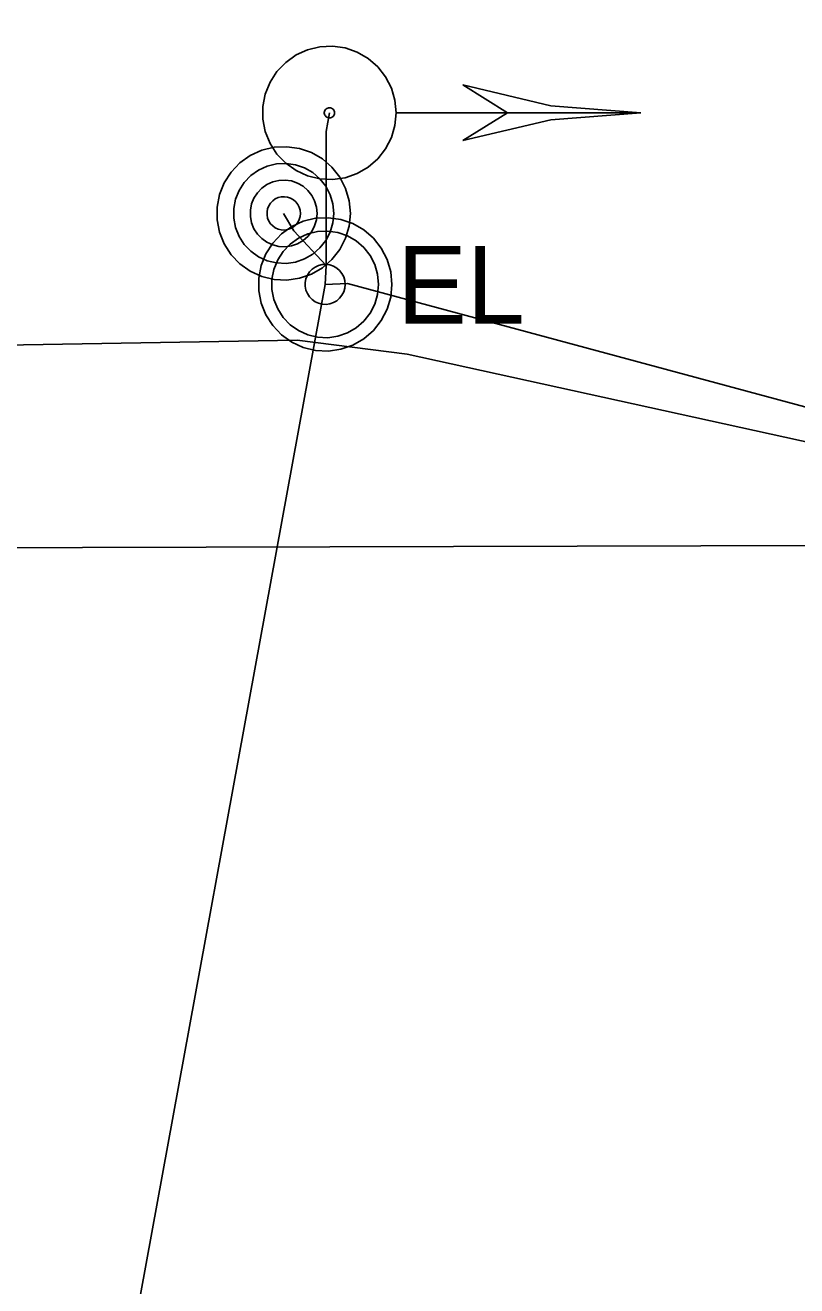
# Model space of a CAD drawing. Extents: x 600849 to 606371, y 330010 to 403088.
# Drawn here: x 604019.5 to 604057.6, y 339253 to 339315.3 of the extents above; entities that cross this region are included whole.
import ezdxf

# ---------------------------------------------------------------- set-up
doc = ezdxf.new("R2010")
doc.units = 0
for name, color, linetype in [('E_MISCPROP', 7, 'Continuous'), ('E_SIG', 7, 'Continuous'), ('E_SIG_Conduit', 7, 'Continuous'), ('E_UTL_E', 7, 'Continuous'), ('E_UTL_E_UG', 7, 'Continuous'), ('E_UTL_T_UG', 7, 'Continuous')]:
    doc.layers.add(name, color=color, linetype=linetype)

msp = doc.modelspace()

# ---------------------------------------------------------------- linework, layer by layer
at = {"layer": 'E_MISCPROP'}
for points in [[(604035.542, 339305.951), (604035.483, 339306.576), (604035.306, 339307.178), (604035.018, 339307.735), (604034.631, 339308.228), (604034.156, 339308.639), (604033.613, 339308.953), (604033.02, 339309.158), (604032.399, 339309.247), (604031.773, 339309.218), (604031.163, 339309.07), (604030.592, 339308.809), (604030.081, 339308.445), (604029.648, 339307.991), (604029.309, 339307.463), (604029.076, 339306.881), (604028.957, 339306.265), (604028.957, 339305.637), (604029.076, 339305.021), (604029.309, 339304.439), (604029.648, 339303.911), (604030.081, 339303.457), (604030.592, 339303.093), (604031.163, 339302.833), (604031.773, 339302.685), (604032.399, 339302.655), (604033.02, 339302.744), (604033.613, 339302.949), (604034.156, 339303.263), (604034.631, 339303.674), (604035.018, 339304.167), (604035.306, 339304.725), (604035.483, 339305.327), (604035.542, 339305.951)], [(604034.717, 339305.951), (604034.673, 339306.42), (604034.54, 339306.871), (604034.324, 339307.289), (604034.034, 339307.659), (604033.678, 339307.967), (604033.27, 339308.202), (604032.826, 339308.356), (604032.36, 339308.423), (604031.89, 339308.401), (604031.433, 339308.29), (604031.005, 339308.095), (604030.622, 339307.822), (604030.297, 339307.481), (604030.042, 339307.085), (604029.868, 339306.648), (604029.778, 339306.186), (604029.778, 339305.716), (604029.868, 339305.254), (604030.042, 339304.817), (604030.297, 339304.421), (604030.622, 339304.081), (604031.005, 339303.808), (604031.433, 339303.612), (604031.89, 339303.501), (604032.36, 339303.479), (604032.826, 339303.546), (604033.27, 339303.7), (604033.678, 339303.935), (604034.034, 339304.243), (604034.324, 339304.613), (604034.54, 339305.031), (604034.673, 339305.483), (604034.717, 339305.951)], [(604033.892, 339305.951), (604033.862, 339306.263), (604033.774, 339306.564), (604033.63, 339306.843), (604033.436, 339307.09), (604033.199, 339307.295), (604032.928, 339307.452), (604032.631, 339307.555), (604032.321, 339307.599), (604032.007, 339307.584), (604031.703, 339307.51), (604031.417, 339307.38), (604031.162, 339307.198), (604030.945, 339306.971), (604030.776, 339306.707), (604030.659, 339306.416), (604030.6, 339306.108), (604030.6, 339305.794), (604030.659, 339305.486), (604030.776, 339305.195), (604030.945, 339304.931), (604031.162, 339304.704), (604031.417, 339304.522), (604031.703, 339304.392), (604032.007, 339304.318), (604032.321, 339304.303), (604032.631, 339304.348), (604032.928, 339304.45), (604033.199, 339304.607), (604033.436, 339304.813), (604033.63, 339305.059), (604033.774, 339305.338), (604033.862, 339305.639), (604033.892, 339305.951)], [(604033.067, 339305.951), (604033.052, 339306.107), (604033.008, 339306.258), (604032.936, 339306.397), (604032.839, 339306.52), (604032.721, 339306.623), (604032.585, 339306.702), (604032.437, 339306.753), (604032.282, 339306.775), (604032.125, 339306.768), (604031.972, 339306.731), (604031.83, 339306.666), (604031.702, 339306.575), (604031.594, 339306.461), (604031.509, 339306.329), (604031.451, 339306.184), (604031.421, 339306.03), (604031.421, 339305.873), (604031.451, 339305.719), (604031.509, 339305.573), (604031.594, 339305.441), (604031.702, 339305.328), (604031.83, 339305.237), (604031.972, 339305.172), (604032.125, 339305.135), (604032.282, 339305.127), (604032.437, 339305.149), (604032.585, 339305.201), (604032.721, 339305.279), (604032.839, 339305.382), (604032.936, 339305.505), (604033.008, 339305.645), (604033.052, 339305.795), (604033.067, 339305.951)]]:
    msp.add_lwpolyline(points, dxfattribs=at)
at = {"layer": 'E_SIG'}
for points in [[(604037.803, 339310.921), (604037.743, 339311.545), (604037.566, 339312.147), (604037.279, 339312.705), (604036.891, 339313.198), (604036.417, 339313.609), (604035.874, 339313.923), (604035.281, 339314.128), (604034.66, 339314.217), (604034.033, 339314.187), (604033.423, 339314.039), (604032.853, 339313.779), (604032.342, 339313.415), (604031.909, 339312.961), (604031.57, 339312.433), (604031.336, 339311.851), (604031.218, 339311.235), (604031.218, 339310.607), (604031.336, 339309.991), (604031.57, 339309.409), (604031.909, 339308.881), (604032.342, 339308.427), (604032.853, 339308.063), (604033.423, 339307.802), (604034.033, 339307.654), (604034.66, 339307.625), (604035.281, 339307.714), (604035.874, 339307.919), (604036.417, 339308.233), (604036.891, 339308.644), (604037.279, 339309.137), (604037.566, 339309.694), (604037.743, 339310.296), (604037.803, 339310.921)], [(604043.303, 339310.92), (604041.103, 339312.297)], [(604049.903, 339310.921), (604045.449, 339311.267), (604041.103, 339312.296)], [(604034.755, 339310.921), (604034.751, 339310.969), (604034.737, 339311.015), (604034.715, 339311.057), (604034.685, 339311.095), (604034.649, 339311.126), (604034.608, 339311.15), (604034.562, 339311.166), (604034.515, 339311.173), (604034.467, 339311.171), (604034.42, 339311.159), (604034.377, 339311.139), (604034.337, 339311.112), (604034.304, 339311.077), (604034.278, 339311.037), (604034.261, 339310.992), (604034.251, 339310.945), (604034.251, 339310.897), (604034.261, 339310.85), (604034.278, 339310.805), (604034.304, 339310.765), (604034.337, 339310.73), (604034.377, 339310.702), (604034.42, 339310.682), (604034.467, 339310.671), (604034.515, 339310.669), (604034.562, 339310.676), (604034.608, 339310.691), (604034.649, 339310.715), (604034.685, 339310.747), (604034.715, 339310.784), (604034.737, 339310.827), (604034.751, 339310.873), (604034.755, 339310.921)], [(604049.902, 339310.92), (604037.861, 339310.92)], [(604049.903, 339310.921), (604045.449, 339310.575), (604041.103, 339309.546)], [(604041.103, 339309.548), (604043.303, 339310.92)]]:
    msp.add_lwpolyline(points, dxfattribs=at)
at = {"layer": 'E_SIG_Conduit'}
msp.add_lwpolyline([(604071.892, 339291.801), (604067.502, 339292.591), (604038.342, 339299.001), (604032.902, 339299.691), (603983.63, 339298.839), (603940.372, 339298.091), (603941.812, 339302.101), (603953.592, 339343.861), (603947.372, 339356.301)], dxfattribs=at)
at = {"layer": 'E_UTL_E'}
for points in [[(604037.594, 339302.443), (604037.534, 339303.067), (604037.357, 339303.669), (604037.07, 339304.227), (604036.682, 339304.72), (604036.208, 339305.131), (604035.664, 339305.444), (604035.072, 339305.65), (604034.451, 339305.739), (604033.824, 339305.709), (604033.214, 339305.561), (604032.644, 339305.3), (604032.133, 339304.937), (604031.7, 339304.482), (604031.36, 339303.955), (604031.127, 339303.372), (604031.009, 339302.756), (604031.009, 339302.129), (604031.127, 339301.513), (604031.36, 339300.93), (604031.7, 339300.403), (604032.133, 339299.949), (604032.644, 339299.585), (604033.214, 339299.324), (604033.824, 339299.176), (604034.451, 339299.146), (604035.072, 339299.236), (604035.664, 339299.441), (604036.208, 339299.754), (604036.682, 339300.165), (604037.07, 339300.658), (604037.357, 339301.216), (604037.534, 339301.818), (604037.594, 339302.443)], [(604037.594, 339302.443), (604037.534, 339303.067), (604037.357, 339303.669), (604037.07, 339304.227), (604036.682, 339304.72), (604036.208, 339305.131), (604035.664, 339305.444), (604035.072, 339305.65), (604034.451, 339305.739), (604033.824, 339305.709), (604033.214, 339305.561), (604032.644, 339305.3), (604032.133, 339304.937), (604031.7, 339304.482), (604031.36, 339303.955), (604031.127, 339303.372), (604031.009, 339302.756), (604031.009, 339302.129), (604031.127, 339301.513), (604031.36, 339300.93), (604031.7, 339300.403), (604032.133, 339299.949), (604032.644, 339299.585), (604033.214, 339299.324), (604033.824, 339299.176), (604034.451, 339299.146), (604035.072, 339299.236), (604035.664, 339299.441), (604036.208, 339299.754), (604036.682, 339300.165), (604037.07, 339300.658), (604037.357, 339301.216), (604037.534, 339301.818), (604037.594, 339302.443)], [(604036.934, 339302.443), (604036.886, 339302.942), (604036.744, 339303.424), (604036.515, 339303.87), (604036.204, 339304.264), (604035.825, 339304.593), (604035.39, 339304.844), (604034.916, 339305.008), (604034.419, 339305.08), (604033.918, 339305.056), (604033.43, 339304.937), (604032.974, 339304.729), (604032.565, 339304.438), (604032.218, 339304.074), (604031.947, 339303.652), (604031.761, 339303.186), (604031.666, 339302.693), (604031.666, 339302.192), (604031.761, 339301.699), (604031.947, 339301.233), (604032.218, 339300.811), (604032.565, 339300.447), (604032.974, 339300.156), (604033.43, 339299.948), (604033.918, 339299.829), (604034.419, 339299.806), (604034.916, 339299.877), (604035.39, 339300.041), (604035.825, 339300.292), (604036.204, 339300.621), (604036.515, 339301.015), (604036.744, 339301.461), (604036.886, 339301.943), (604036.934, 339302.443)], [(604036.934, 339302.443), (604036.886, 339302.942), (604036.744, 339303.424), (604036.515, 339303.87), (604036.204, 339304.264), (604035.825, 339304.593), (604035.39, 339304.844), (604034.916, 339305.008), (604034.419, 339305.08), (604033.918, 339305.056), (604033.43, 339304.937), (604032.974, 339304.729), (604032.565, 339304.438), (604032.218, 339304.074), (604031.947, 339303.652), (604031.761, 339303.186), (604031.666, 339302.693), (604031.666, 339302.192), (604031.761, 339301.699), (604031.947, 339301.233), (604032.218, 339300.811), (604032.565, 339300.447), (604032.974, 339300.156), (604033.43, 339299.948), (604033.918, 339299.829), (604034.419, 339299.806), (604034.916, 339299.877), (604035.39, 339300.041), (604035.825, 339300.292), (604036.204, 339300.621), (604036.515, 339301.015), (604036.744, 339301.461), (604036.886, 339301.943), (604036.934, 339302.443)], [(604035.284, 339302.443), (604035.266, 339302.63), (604035.213, 339302.81), (604035.126, 339302.978), (604035.01, 339303.126), (604034.868, 339303.249), (604034.705, 339303.343), (604034.527, 339303.405), (604034.341, 339303.431), (604034.153, 339303.422), (604033.97, 339303.378), (604033.799, 339303.3), (604033.645, 339303.191), (604033.515, 339303.055), (604033.414, 339302.896), (604033.344, 339302.721), (604033.308, 339302.537), (604033.308, 339302.348), (604033.344, 339302.164), (604033.414, 339301.989), (604033.515, 339301.831), (604033.645, 339301.694), (604033.799, 339301.585), (604033.97, 339301.507), (604034.153, 339301.463), (604034.341, 339301.454), (604034.527, 339301.48), (604034.705, 339301.542), (604034.868, 339301.636), (604035.01, 339301.759), (604035.126, 339301.907), (604035.213, 339302.075), (604035.266, 339302.255), (604035.284, 339302.443)], [(604035.284, 339302.443), (604035.266, 339302.63), (604035.213, 339302.81), (604035.126, 339302.978), (604035.01, 339303.126), (604034.868, 339303.249), (604034.705, 339303.343), (604034.527, 339303.405), (604034.341, 339303.431), (604034.153, 339303.422), (604033.97, 339303.378), (604033.799, 339303.3), (604033.645, 339303.191), (604033.515, 339303.055), (604033.414, 339302.896), (604033.344, 339302.721), (604033.308, 339302.537), (604033.308, 339302.348), (604033.344, 339302.164), (604033.414, 339301.989), (604033.515, 339301.831), (604033.645, 339301.694), (604033.799, 339301.585), (604033.97, 339301.507), (604034.153, 339301.463), (604034.341, 339301.454), (604034.527, 339301.48), (604034.705, 339301.542), (604034.868, 339301.636), (604035.01, 339301.759), (604035.126, 339301.907), (604035.213, 339302.075), (604035.266, 339302.255), (604035.284, 339302.443)]]:
    msp.add_lwpolyline(points, dxfattribs=at)
at = {"layer": 'E_UTL_E_UG'}
for points in [[(604034.342, 339303.381), (604034.342, 339310.001), (604034.502, 339310.921)], [(604071.892, 339291.801), (604068.452, 339293.571), (604035.402, 339302.481), (604034.292, 339302.441), (604034.342, 339303.381), (604032.742, 339305.081), (604032.242, 339305.951)], [(604104.462, 339015.892), (604090.959, 339040.272), (604077.261, 339062.296), (604070.632, 339081.862), (604055.372, 339128.142), (604048.992, 339151.002), (604037.262, 339191.412), (604036.512, 339193.092), (604036.312, 339194.342), (604031.922, 339203.072), (604031.512, 339204.012), (604023.302, 339242.342), (604034.292, 339302.441)]]:
    msp.add_lwpolyline(points, dxfattribs=at)
at = {"layer": 'E_UTL_T_UG'}
msp.add_lwpolyline([(603714.183, 339271.321), (603782.13, 339275.191), (603820.542, 339288.901), (604303.519, 339290.202)], dxfattribs=at)

# ---------------------------------------------------------------- texts
at = {"layer": 'E_UTL_E'}
msp.add_text('EL', height=3.8491, dxfattribs=at).set_placement((604037.858, 339300.497))
msp.add_text('EL', height=3.8491, dxfattribs=at).set_placement((604037.858, 339300.497))

doc.saveas('drawing.dxf')
